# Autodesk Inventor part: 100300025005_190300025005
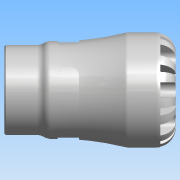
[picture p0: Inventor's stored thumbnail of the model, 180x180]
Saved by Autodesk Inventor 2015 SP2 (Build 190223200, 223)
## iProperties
Created: 2016-12
Part Number: 100300025005_190300025005
Material: PVC-Piping
Description: PLASSON FEMALE ADAPTOR 25X1/2" SERIES 1
Document SubType Name: Modeling
Designer: KIM
Mass: 664.223 g
Surface Area: 733.008 cm^2
Volume: 474.445 cm^3
Density: 1.4 g/cm^3
Appearance: Smooth - White
Author: KIM
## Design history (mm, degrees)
derived "1003.ipt"
feature "Solid1::1003.ipt"
tag "TaggingFeature1"
body "Solid1"
other parameters: "d1" = 20.16, "d2" = 25, "d3" = 31.25, "d4" = 47, "d6" = 48, "d8" = 39.95, "d13" = 6.3, "d14" = 6.3, "d15" = 0, "d17" = 360 deg, "d19" = 8 deg, "d20" = 0.5, "d21" = 0.5, "d22" = 8 deg, "d24" = 0, "d26" = 360 deg, "d32" = 4.7, "d33" = 4.7, "d39" = 0.55893, "d42" = 18.631, "d43" = 36.66, "d46" = 2.08333, "d47" = 17, "d48" = 17.69945, "d50" = 1.65, "d51" = 0.47, "d54" = 8.75, "d55" = 5.5, "d57" = 12.348, "d58" = 0, "d68" = 360 deg, "d72" = 0.5, "d74" = 0, "d76" = 7.4375, "d_" = 25, "E_" = 47, "l_" = 48, "Rp" = 18.631, "l_2" = 17, "d9" = 7.875, "d11" = 47, "d12" = 31.25, "d49" = 5
